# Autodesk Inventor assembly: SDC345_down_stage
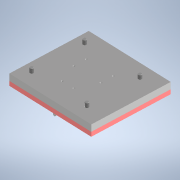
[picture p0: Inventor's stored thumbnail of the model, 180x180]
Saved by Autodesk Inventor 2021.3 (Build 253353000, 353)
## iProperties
Created: 2022-02
Part Number: SDC345_down_stage
Document SubType Name: Assembly
Designer: kengo
Author: kengo
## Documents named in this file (8)
- C:\Users\kengo\Documents\S2S_frame\SDC345\frame_misumi_ver12\stage\SDC345_down_stage.iam
- C:\Users\kengo\Documents\S2S_frame\SDC345\frame_misumi_ver12\stage\SDC3_Delstage.ipt
- C:\Users\kengo\Documents\S2S_frame\SDC345\frame_misumi_ver12\stage\SDC345_Alstage.ipt
- C:\Users\kengo\Documents\S2S_frame\SDC345\frame_misumi_ver12\stage\SCB8-15.ipt
- C:\Users\kengo\Documents\S2S_frame\SDC345\frame_misumi_ver12\stage\SCB8-35.ipt
- C:\Users\kengo\Documents\S2S_frame\SDC345\frame_misumi_ver12\stage\AJSN8-20.ipt
- C:\Users\kengo\Documents\S2S_frame\SDC345\frame_misumi_ver12\stage\SCB6-50.ipt
- C:\Users\kengo\Documents\S2S_frame\SDC345\frame_misumi_ver12\upper-stage\UNST8-40.iam
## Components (18 placed, 7 different names)
1. SDC3_Delstage:1 — メイト:1, フラッシュ:1, フラッシュ:2, リジッド:1, 回転:2, 回転:3, 挿入:1, 挿入:2, 挿入:3
2. SDC345_Alstage:1 — メイト:1, 回転:1, フラッシュ:1, フラッシュ:2, 回転:10
3. SCB8-15:1 — 回転:1
4. SCB8-35:1 — リジッド:1
5. SCB8-35:2 — 回転:2
6. SCB8-35:3 — 回転:3
7. AJSN8-20:1 — 挿入:2, 回転:6, 回転:7, 回転:11
8. AJSN8-20:2 — 挿入:3, 回転:4, 回転:5, 回転:12
9. AJSN8-20:3 — 挿入:1, 回転:8, 回転:9, リジッド:2
10. SCB6-50:1 — 回転:4
11. SCB6-50:2 — 回転:5
12. SCB6-50:3 — 回転:6
13. SCB6-50:4 — 回転:7, 回転:10
14. SCB6-50:5 — 回転:8
15. SCB6-50:6 — 回転:9
16. UNST8-40:1 [sub-assembly] — 回転:11
17. UNST8-40:2 [sub-assembly] — 回転:12
18. UNST8-40:3 [sub-assembly] — リジッド:2
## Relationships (20: RevoluteJoint 12, Insert 3, Flush 2, WeldJoint 2, Mate 1)
- メイト:1 [Mate]: SDC3_Delstage:1 ↔ SDC345_Alstage:1
- 回転:1 [RevoluteJoint]: SDC345_Alstage:1 ↔ SCB8-15:1
- フラッシュ:1 [Flush]: SDC3_Delstage:1 ↔ SDC345_Alstage:1
- フラッシュ:2 [Flush]: SDC3_Delstage:1 ↔ SDC345_Alstage:1
- リジッド:1 [WeldJoint]: SDC3_Delstage:1 ↔ SCB8-35:1
- 回転:2 [RevoluteJoint]: SDC3_Delstage:1 ↔ SCB8-35:2
- 回転:3 [RevoluteJoint]: SDC3_Delstage:1 ↔ SCB8-35:3
- 挿入:1 [Insert]: SDC3_Delstage:1 ↔ AJSN8-20:3
- 挿入:2 [Insert]: SDC3_Delstage:1 ↔ AJSN8-20:1
- 挿入:3 [Insert]: SDC3_Delstage:1 ↔ AJSN8-20:2
- 回転:4 [RevoluteJoint]: AJSN8-20:2 ↔ SCB6-50:1
- 回転:5 [RevoluteJoint]: AJSN8-20:2 ↔ SCB6-50:2
- 回転:6 [RevoluteJoint]: AJSN8-20:1 ↔ SCB6-50:3
- 回転:7 [RevoluteJoint]: AJSN8-20:1 ↔ SCB6-50:4
- 回転:8 [RevoluteJoint]: AJSN8-20:3 ↔ SCB6-50:5
- 回転:9 [RevoluteJoint]: AJSN8-20:3 ↔ SCB6-50:6
- 回転:10 [RevoluteJoint]: SDC345_Alstage:1 ↔ SCB6-50:4
- 回転:11 [RevoluteJoint]: AJSN8-20:1 ↔ UNST8-40:1
- リジッド:2 [WeldJoint]: AJSN8-20:3 ↔ UNST8-40:3
- 回転:12 [RevoluteJoint]: AJSN8-20:2 ↔ UNST8-40:2
